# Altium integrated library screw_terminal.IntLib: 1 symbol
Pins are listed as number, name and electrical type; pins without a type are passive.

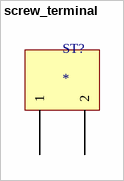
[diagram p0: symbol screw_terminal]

## screw_terminal
designator ST?
footprint screw_terminal_5
pins: 1, 2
